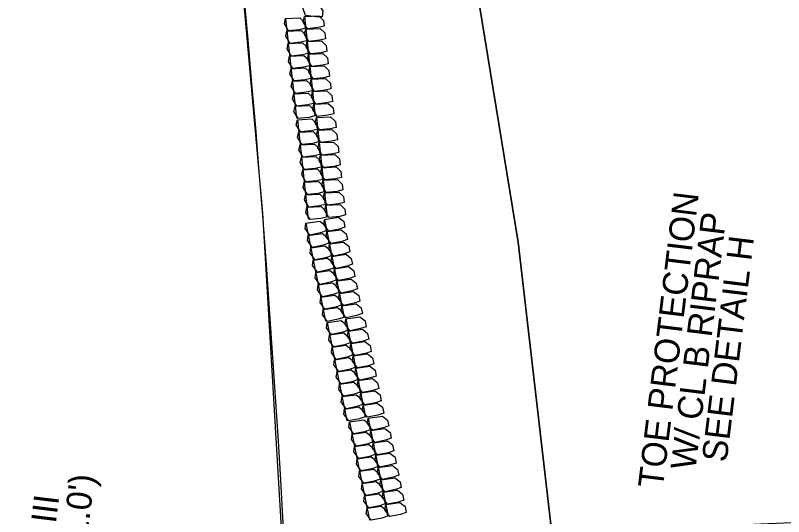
# Model space of a CAD drawing. Extents: x 465700 to 483515, y 488970 to 507540.
# Drawn here: x 481299.7 to 481453, y 491524 to 491624.1 of the extents above; entities that cross this region are included whole.
import ezdxf

# ---------------------------------------------------------------- set-up
doc = ezdxf.new("R2010")
doc.units = 0
for name, color, linetype in [('Default', 7, 'Continuous'), ('Exist Plan Preparation Watershed Blue', 7, 'Continuous'), ('Prop Drainage Structure Pipe RCP 48in Class III Label', 7, 'Continuous'), ('Prop Erosion Embankment Toe Protection CELL', 7, 'Continuous'), ('Prop Erosion Embankment Toe Protection Label', 7, 'Continuous')]:
    doc.layers.add(name, color=color, linetype=linetype)

msp = doc.modelspace()

# ---------------------------------------------------------------- linework, layer by layer
at = {"layer": 'Default'}
msp.add_arc((478448.2, 491360.26), 2909.5, 356.95228, 8.055, dxfattribs=at)
at = {"layer": 'Exist Plan Preparation Watershed Blue'}
for points in [[(481351.25, 491164.11), (481355.63, 491237.92), (481357.02, 491295.88), (481357.71, 491377.55), (481356.61, 491435.42), (481354.34, 491495.85), (481349.13, 491584.55), (481341.19, 491673.05), (481328.95, 491769.45), (481331.36, 491785.24), (481338.28, 491786.26), (481358.32, 491790.73), (481372.6, 491727.76), (481383.56, 491677.38), (481390.7, 491636.27), (481400.08, 491578.77), (481407.45, 491514.97), (481410.05, 491479.29), (481411.52, 491442.54), (481412.58, 491412.05), (481413.67, 491377.22), (481412.27, 491323.04), (481409.74, 491273.14), (481400.35, 491179.93)], [(481786.78, 491759.9), (481568.07, 491531.08), (481568.07, 491531.08), (481568.07, 491531.08), (481568.07, 491531.08), (481489.54, 491524.26), (481441, 491522.17), (481441, 491522.17), (481407.45, 491514.97), (481400.08, 491578.77), (481390.7, 491636.27)]]:
    msp.add_lwpolyline(points, dxfattribs=at)
at = {"layer": 'Prop Erosion Embankment Toe Protection CELL'}
for p, q in [((481353.64, 491623.4), (481355.8, 491603.52)), ((481357.41, 491623.81), (481359.57, 491603.93)), ((481356, 491603.22), (481358.16, 491583.34)), ((481359.78, 491603.64), (481361.94, 491583.75)), ((481357.68, 491582.58), (481361.63, 491562.98)), ((481361.4, 491583.33), (481365.35, 491563.73)), ((481361.93, 491562.71), (481365.88, 491543.11)), ((481365.65, 491563.46), (481369.6, 491543.86)), ((481366.42, 491542.9), (481370.37, 491523.29)), ((481370.15, 491543.65), (481374.1, 491524.05))]:
    msp.add_line(p, q, dxfattribs=at)
for points in [[(481360.94, 491623.77), (481359.73, 491623.76), (481357.6, 491624), (481357.07, 491625.57), (481357.53, 491626.52), (481360.34, 491626.05), (481361.08, 491624.97), (481360.94, 491623.77)], [(481361.35, 491621.88), (481360.17, 491621.6), (481358.03, 491621.37), (481357.17, 491622.78), (481357.41, 491623.81), (481360.26, 491623.97), (481361.22, 491623.05), (481361.35, 491621.88)], [(481357.57, 491621.47), (481356.39, 491621.19), (481354.25, 491620.96), (481353.4, 491622.37), (481353.64, 491623.4), (481356.49, 491623.56), (481357.44, 491622.64), (481357.57, 491621.47)], [(481357.84, 491618.98), (481356.66, 491618.68), (481354.53, 491618.45), (481353.67, 491619.89), (481353.91, 491620.92), (481356.76, 491621.05), (481357.71, 491620.12), (481357.84, 491618.98)], [(481361.62, 491619.39), (481360.44, 491619.09), (481358.3, 491618.86), (481357.44, 491620.3), (481357.68, 491621.33), (481360.54, 491621.46), (481361.49, 491620.54), (481361.62, 491619.39)], [(481358.11, 491616.47), (481356.94, 491616.17), (481354.8, 491615.94), (481353.94, 491617.38), (481354.18, 491618.41), (481357.03, 491618.54), (481357.98, 491617.64), (481358.11, 491616.47)], [(481361.89, 491616.88), (481360.71, 491616.58), (481358.58, 491616.35), (481357.72, 491617.79), (481357.96, 491618.82), (481360.81, 491618.95), (481361.76, 491618.05), (481361.89, 491616.88)], [(481362.16, 491614.37), (481360.98, 491614.09), (481358.85, 491613.86), (481357.99, 491615.28), (481358.23, 491616.31), (481361.08, 491616.47), (481362.03, 491615.56), (481362.16, 491614.37)], [(481358.38, 491613.96), (481357.21, 491613.68), (481355.07, 491613.45), (481354.21, 491614.87), (481354.45, 491615.9), (481357.3, 491616.06), (481358.25, 491615.15), (481358.38, 491613.96)], [(481358.65, 491611.48), (481357.48, 491611.2), (481355.34, 491610.96), (481354.48, 491612.38), (481354.72, 491613.41), (481357.57, 491613.57), (481358.53, 491612.64), (481358.65, 491611.48)], [(481362.43, 491611.89), (481361.25, 491611.61), (481359.12, 491611.38), (481358.26, 491612.79), (481358.5, 491613.82), (481361.35, 491613.98), (481362.3, 491613.05), (481362.43, 491611.89)], [(481358.92, 491608.99), (481357.75, 491608.69), (481355.61, 491608.45), (481354.75, 491609.9), (481354.99, 491610.93), (481357.84, 491611.06), (481358.8, 491610.13), (481358.92, 491608.99)], [(481362.7, 491609.4), (481361.53, 491609.1), (481359.39, 491608.87), (481358.53, 491610.31), (481358.77, 491611.34), (481361.62, 491611.47), (481362.58, 491610.54), (481362.7, 491609.4)], [(481362.97, 491606.89), (481361.8, 491606.59), (481359.66, 491606.35), (481358.8, 491607.8), (481359.04, 491608.83), (481361.89, 491608.96), (481362.85, 491608.06), (481362.97, 491606.89)], [(481359.2, 491606.48), (481358.02, 491606.18), (481355.88, 491605.94), (481355.02, 491607.38), (481355.26, 491608.42), (481358.12, 491608.55), (481359.07, 491607.65), (481359.2, 491606.48)], [(481359.47, 491603.97), (481358.29, 491603.69), (481356.15, 491603.46), (481355.3, 491604.87), (481355.54, 491605.91), (481358.39, 491606.07), (481359.34, 491605.16), (481359.47, 491603.97)], [(481363.25, 491604.38), (481362.07, 491604.1), (481359.93, 491603.87), (481359.07, 491605.29), (481359.31, 491606.32), (481362.16, 491606.48), (481363.12, 491605.57), (481363.25, 491604.38)], [(481359.93, 491601.29), (481358.76, 491601.01), (481356.62, 491600.78), (481355.76, 491602.19), (481356, 491603.22), (481358.85, 491603.38), (481359.81, 491602.46), (481359.93, 491601.29)], [(481363.71, 491601.7), (481362.53, 491601.42), (481360.4, 491601.19), (481359.54, 491602.6), (481359.78, 491603.64), (481362.63, 491603.79), (481363.58, 491602.87), (481363.71, 491601.7)], [(481363.98, 491599.21), (481362.81, 491598.91), (481360.67, 491598.68), (481359.81, 491600.12), (481360.05, 491601.15), (481362.9, 491601.28), (481363.86, 491600.36), (481363.98, 491599.21)], [(481360.2, 491598.8), (481359.03, 491598.5), (481356.89, 491598.27), (481356.03, 491599.71), (481356.27, 491600.74), (481359.12, 491600.87), (481360.08, 491599.95), (481360.2, 491598.8)], [(481360.48, 491596.29), (481359.3, 491595.99), (481357.16, 491595.76), (481356.3, 491597.2), (481356.54, 491598.23), (481359.4, 491598.36), (481360.35, 491597.46), (481360.48, 491596.29)], [(481364.25, 491596.7), (481363.08, 491596.4), (481360.94, 491596.17), (481360.08, 491597.61), (481360.32, 491598.64), (481363.17, 491598.77), (481364.13, 491597.87), (481364.25, 491596.7)], [(481360.75, 491593.78), (481359.57, 491593.5), (481357.43, 491593.27), (481356.58, 491594.69), (481356.82, 491595.72), (481359.67, 491595.88), (481360.62, 491594.98), (481360.75, 491593.78)], [(481364.53, 491594.19), (481363.35, 491593.91), (481361.21, 491593.68), (481360.35, 491595.1), (481360.59, 491596.13), (481363.44, 491596.29), (481364.4, 491595.39), (481364.53, 491594.19)], [(481361.02, 491591.3), (481359.84, 491591.02), (481357.7, 491590.79), (481356.85, 491592.2), (481357.09, 491593.23), (481359.94, 491593.39), (481360.89, 491592.46), (481361.02, 491591.3)], [(481364.8, 491591.71), (481363.62, 491591.43), (481361.48, 491591.2), (481360.62, 491592.61), (481360.86, 491593.64), (481363.71, 491593.8), (481364.67, 491592.88), (481364.8, 491591.71)], [(481361.29, 491588.81), (481360.11, 491588.51), (481357.98, 491588.28), (481357.12, 491589.72), (481357.36, 491590.75), (481360.21, 491590.88), (481361.16, 491589.95), (481361.29, 491588.81)], [(481365.07, 491589.22), (481363.89, 491588.92), (481361.76, 491588.69), (481360.89, 491590.13), (481361.13, 491591.16), (481363.99, 491591.29), (481364.94, 491590.37), (481365.07, 491589.22)], [(481365.34, 491586.71), (481364.17, 491586.41), (481362.03, 491586.18), (481361.17, 491587.62), (481361.41, 491588.65), (481364.26, 491588.78), (481365.21, 491587.88), (481365.34, 491586.71)], [(481361.56, 491586.3), (481360.39, 491586), (481358.25, 491585.77), (481357.39, 491587.21), (481357.63, 491588.24), (481360.48, 491588.37), (481361.43, 491587.47), (481361.56, 491586.3)], [(481361.83, 491583.79), (481360.66, 491583.51), (481358.52, 491583.28), (481357.66, 491584.7), (481357.9, 491585.73), (481360.75, 491585.89), (481361.7, 491584.98), (481361.83, 491583.79)], [(481365.61, 491584.2), (481364.44, 491583.92), (481362.3, 491583.69), (481361.44, 491585.11), (481361.68, 491586.14), (481364.53, 491586.3), (481365.48, 491585.39), (481365.61, 491584.2)], [(481361.77, 491581.01), (481360.62, 491580.62), (481358.51, 491580.2), (481357.53, 491581.53), (481357.68, 491582.58), (481360.5, 491583), (481361.54, 491582.16), (481361.77, 491581.01)], [(481365.49, 491581.76), (481364.35, 491581.38), (481362.24, 491580.95), (481361.26, 491582.28), (481361.4, 491583.33), (481364.23, 491583.75), (481365.26, 491582.91), (481365.49, 491581.76)], [(481365.99, 491579.31), (481364.85, 491578.9), (481362.74, 491578.48), (481361.75, 491579.83), (481361.9, 491580.88), (481364.72, 491581.27), (481365.76, 491580.44), (481365.99, 491579.31)], [(481362.26, 491578.56), (481361.12, 491578.15), (481359.01, 491577.72), (481358.03, 491579.08), (481358.17, 491580.13), (481361, 491580.52), (481362.04, 491579.69), (481362.26, 491578.56)], [(481362.76, 491576.08), (481361.62, 491575.67), (481359.51, 491575.25), (481358.52, 491576.61), (481358.67, 491577.66), (481361.5, 491578.05), (481362.53, 491577.23), (481362.76, 491576.08)], [(481366.49, 491576.83), (481365.34, 491576.42), (481363.24, 491576), (481362.25, 491577.36), (481362.4, 491578.41), (481365.22, 491578.8), (481366.25, 491577.99), (481366.49, 491576.83)], [(481363.26, 491573.61), (481362.11, 491573.22), (481360.01, 491572.8), (481359.02, 491574.13), (481359.17, 491575.18), (481361.99, 491575.6), (481363.02, 491574.78), (481363.26, 491573.61)], [(481366.99, 491574.36), (481365.84, 491573.97), (481363.73, 491573.55), (481362.75, 491574.88), (481362.89, 491575.93), (481365.72, 491576.35), (481366.75, 491575.53), (481366.99, 491574.36)], [(481367.48, 491571.91), (481366.33, 491571.52), (481364.22, 491571.1), (481363.24, 491572.43), (481363.39, 491573.48), (481366.21, 491573.9), (481367.25, 491573.06), (481367.48, 491571.91)], [(481363.75, 491571.16), (481362.61, 491570.77), (481360.5, 491570.35), (481359.52, 491571.68), (481359.66, 491572.73), (481362.49, 491573.15), (481363.52, 491572.31), (481363.75, 491571.16)], [(481364.25, 491568.71), (481363.11, 491568.3), (481361, 491567.87), (481360.01, 491569.23), (481360.16, 491570.28), (481362.98, 491570.67), (481364.02, 491569.83), (481364.25, 491568.71)], [(481367.97, 491569.46), (481366.83, 491569.05), (481364.72, 491568.62), (481363.74, 491569.98), (481363.88, 491571.03), (481366.71, 491571.42), (481367.75, 491570.58), (481367.97, 491569.46)], [(481368.47, 491566.98), (481367.33, 491566.57), (481365.22, 491566.15), (481364.23, 491567.5), (481364.38, 491568.55), (481367.21, 491568.95), (481368.24, 491568.13), (481368.47, 491566.98)], [(481364.75, 491566.23), (481363.6, 491565.82), (481361.5, 491565.4), (481360.51, 491566.75), (481360.66, 491567.8), (481363.48, 491568.2), (481364.51, 491567.38), (481364.75, 491566.23)], [(481365.25, 491563.76), (481364.1, 491563.37), (481361.99, 491562.95), (481361.01, 491564.28), (481361.15, 491565.33), (481363.98, 491565.74), (481365.01, 491564.93), (481365.25, 491563.76)], [(481368.97, 491564.51), (481367.82, 491564.12), (481365.72, 491563.7), (481364.73, 491565.03), (481364.88, 491566.08), (481367.7, 491566.49), (481368.73, 491565.68), (481368.97, 491564.51)], [(481366.02, 491561.14), (481364.87, 491560.76), (481362.76, 491560.33), (481361.78, 491561.66), (481361.93, 491562.71), (481364.75, 491563.13), (481365.78, 491562.29), (481366.02, 491561.14)], [(481369.74, 491561.89), (481368.59, 491561.51), (481366.49, 491561.08), (481365.5, 491562.41), (481365.65, 491563.46), (481368.47, 491563.88), (481369.51, 491563.04), (481369.74, 491561.89)], [(481370.24, 491559.44), (481369.09, 491559.03), (481366.99, 491558.61), (481366, 491559.96), (481366.14, 491561.01), (481368.97, 491561.4), (481370.01, 491560.57), (481370.24, 491559.44)], [(481366.51, 491558.69), (481365.37, 491558.28), (481363.26, 491557.86), (481362.27, 491559.21), (481362.42, 491560.26), (481365.25, 491560.65), (481366.28, 491559.82), (481366.51, 491558.69)], [(481367.01, 491556.21), (481365.87, 491555.81), (481363.76, 491555.38), (481362.77, 491556.74), (481362.92, 491557.79), (481365.75, 491558.18), (481366.78, 491557.37), (481367.01, 491556.21)], [(481370.73, 491556.97), (481369.59, 491556.56), (481367.48, 491556.13), (481366.5, 491557.49), (481366.64, 491558.54), (481369.47, 491558.93), (481370.5, 491558.12), (481370.73, 491556.97)], [(481371.23, 491554.49), (481370.09, 491554.11), (481367.98, 491553.68), (481367, 491555.01), (481367.14, 491556.06), (481369.97, 491556.48), (481371, 491555.67), (481371.23, 491554.49)], [(481367.51, 491553.74), (481366.36, 491553.36), (481364.25, 491552.93), (481363.27, 491554.26), (481363.42, 491555.31), (481366.24, 491555.73), (481367.27, 491554.92), (481367.51, 491553.74)], [(481371.73, 491552.04), (481370.58, 491551.66), (481368.47, 491551.23), (481367.49, 491552.56), (481367.64, 491553.61), (481370.46, 491554.03), (481371.49, 491553.19), (481371.73, 491552.04)], [(481368, 491551.29), (481366.86, 491550.9), (481364.75, 491550.48), (481363.76, 491551.81), (481363.91, 491552.86), (481366.73, 491553.28), (481367.77, 491552.44), (481368, 491551.29)], [(481368.5, 491548.84), (481367.35, 491548.43), (481365.25, 491548), (481364.26, 491549.36), (481364.4, 491550.41), (481367.23, 491550.8), (481368.27, 491549.97), (481368.5, 491548.84)], [(481372.22, 491549.59), (481371.08, 491549.18), (481368.97, 491548.76), (481367.98, 491550.11), (481368.13, 491551.16), (481370.96, 491551.55), (481371.99, 491550.72), (481372.22, 491549.59)], [(481372.72, 491547.11), (481371.58, 491546.7), (481369.47, 491546.28), (481368.48, 491547.64), (481368.63, 491548.69), (481371.46, 491549.08), (481372.49, 491548.27), (481372.72, 491547.11)], [(481368.99, 491546.36), (481367.85, 491545.95), (481365.75, 491545.53), (481364.76, 491546.89), (481364.9, 491547.94), (481367.73, 491548.33), (481368.76, 491547.51), (481368.99, 491546.36)], [(481369.49, 491543.89), (481368.35, 491543.5), (481366.24, 491543.08), (481365.26, 491544.41), (481365.4, 491545.46), (481368.23, 491545.88), (481369.26, 491545.06), (481369.49, 491543.89)], [(481373.22, 491544.64), (481372.07, 491544.25), (481369.96, 491543.83), (481368.98, 491545.16), (481369.13, 491546.21), (481371.95, 491546.63), (481372.98, 491545.81), (481373.22, 491544.64)], [(481370.51, 491541.33), (481369.37, 491540.94), (481367.26, 491540.52), (481366.28, 491541.85), (481366.42, 491542.9), (481369.25, 491543.32), (481370.28, 491542.48), (481370.51, 491541.33)], [(481374.24, 491542.08), (481373.09, 491541.69), (481370.98, 491541.27), (481370, 491542.6), (481370.15, 491543.65), (481372.97, 491544.07), (481374.01, 491543.23), (481374.24, 491542.08)], [(481374.73, 491539.63), (481373.59, 491539.22), (481371.48, 491538.79), (481370.5, 491540.15), (481370.64, 491541.2), (481373.47, 491541.59), (481374.51, 491540.75), (481374.73, 491539.63)], [(481371.01, 491538.88), (481369.87, 491538.47), (481367.76, 491538.04), (481366.77, 491539.4), (481366.92, 491540.45), (481369.75, 491540.84), (481370.78, 491540), (481371.01, 491538.88)], [(481371.51, 491536.4), (481370.36, 491535.99), (481368.26, 491535.57), (481367.27, 491536.92), (481367.42, 491537.97), (481370.24, 491538.37), (481371.27, 491537.55), (481371.51, 491536.4)], [(481375.23, 491537.15), (481374.09, 491536.74), (481371.98, 491536.32), (481370.99, 491537.68), (481371.14, 491538.73), (481373.97, 491539.12), (481375, 491538.3), (481375.23, 491537.15)], [(481375.73, 491534.68), (481374.58, 491534.29), (481372.48, 491533.87), (481371.49, 491535.2), (481371.64, 491536.25), (481374.46, 491536.67), (481375.49, 491535.85), (481375.73, 491534.68)], [(481372.01, 491533.93), (481370.86, 491533.54), (481368.75, 491533.12), (481367.77, 491534.45), (481367.91, 491535.5), (481370.74, 491535.92), (481371.77, 491535.1), (481372.01, 491533.93)], [(481372.5, 491531.48), (481371.35, 491531.09), (481369.25, 491530.67), (481368.26, 491532), (481368.41, 491533.05), (481371.23, 491533.46), (481372.27, 491532.63), (481372.5, 491531.48)], [(481376.22, 491532.23), (481375.08, 491531.84), (481372.97, 491531.42), (481371.99, 491532.75), (481372.13, 491533.8), (481374.96, 491534.22), (481375.99, 491533.38), (481376.22, 491532.23)], [(481372.99, 491529.02), (481371.85, 491528.62), (481369.74, 491528.19), (481368.76, 491529.55), (481368.9, 491530.6), (481371.73, 491530.99), (481372.77, 491530.15), (481372.99, 491529.02)], [(481376.72, 491529.78), (481375.58, 491529.37), (481373.47, 491528.94), (481372.48, 491530.3), (481372.63, 491531.35), (481375.46, 491531.74), (481376.49, 491530.9), (481376.72, 491529.78)], [(481377.22, 491527.3), (481376.08, 491526.89), (481373.97, 491526.47), (481372.98, 491527.82), (481373.13, 491528.87), (481375.95, 491529.26), (481376.99, 491528.45), (481377.22, 491527.3)], [(481373.49, 491526.55), (481372.35, 491526.14), (481370.24, 491525.72), (481369.26, 491527.07), (481369.4, 491528.12), (481372.23, 491528.51), (481373.26, 491527.7), (481373.49, 491526.55)], [(481373.99, 491524.07), (481372.84, 491523.69), (481370.74, 491523.27), (481369.75, 491524.6), (481369.9, 491525.65), (481372.72, 491526.06), (481373.75, 491525.25), (481373.99, 491524.07)], [(481377.72, 491524.83), (481376.57, 491524.44), (481374.46, 491524.02), (481373.48, 491525.35), (481373.62, 491526.4), (481376.45, 491526.81), (481377.48, 491526), (481377.72, 491524.83)]]:
    msp.add_lwpolyline(points, dxfattribs=at)

# ---------------------------------------------------------------- texts
at = {"layer": 'Prop Drainage Structure Pipe RCP 48in Class III Label'}
for s, p in [("(BURIED 1.0')", (481310.47, 491490.35)), ('48" RCP-III', (481304.4, 491494.69))]:
    msp.add_text(s, height=5, rotation=83.0365, dxfattribs=at).set_placement(p)
at = {"layer": 'Prop Erosion Embankment Toe Protection Label'}
for s, p in [('TOE PROTECTION', (481428.93, 491529.48)), ('W/ CL B RIPRAP', (481435.42, 491533.13)), ('SEE DETAIL H', (481441.66, 491534.71))]:
    msp.add_text(s, height=5, rotation=83.0365, dxfattribs=at).set_placement(p)

doc.saveas('drawing.dxf')
